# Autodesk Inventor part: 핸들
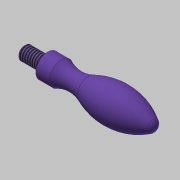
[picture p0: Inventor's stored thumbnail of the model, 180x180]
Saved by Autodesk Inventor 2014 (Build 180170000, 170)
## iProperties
Created: 2019-10
Part Number: 핸들
Material: 스테인리스강
Document SubType Name: Modeling
Designer: mduedu
Density: 1 g/cm^3
Appearance: 보라색
Author: mduedu
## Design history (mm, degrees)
sketch "스케치1"
  geometry: L1 (0, 0)-(0, 2); L2 (0, 2)-(7, 2); L3 (7, 2)-(7, 3.5); L4 (7, 3.5)-(11, 3.5); L5 (0, 0)-(39, 0); A1 r 9.5 centre (15.243, 12) between (11, 3.5) and (19.07, 3.305); A2 r 20 centre (27.128, -15) between (38.049, 1.754) and (19.07, 3.305); A3 r 2.094 centre (36.906, 0) between (39, 0) and (38.049, 1.754)
  constraints: 10 end point, 6 point on circle, 3 centre point, 3 parallel, 2 tangent, 1 perpendicular, 1 point on line, 1 vertical
  dimensions: "d0" = 39 distance of L1.start L5.end; "d1" = 4 diameter of L2 L5; "d2" = 7 diameter of L4 L5; "d3" = 7 distance of L1.end L2.end; "d4" = 4 distance of L3.end L4.end; "d5" = 5 dimension on A1 L5; "d6" = 9.5 radius of A1; "d7" = 10 dimension on A2 L5; "d8" = 20 radius of A2
revolve "회전1" sketch "스케치1" stored, may be unused: angle "d9" = 90 deg
feature "스레드1" dims "d10" = 6, "d11" = 0
chamfer "모따기1" distance "d12" = 0.5; stored, may be unused: second distance "d13" = 2, angle "d14" = 45 deg
node "솔리드1"
